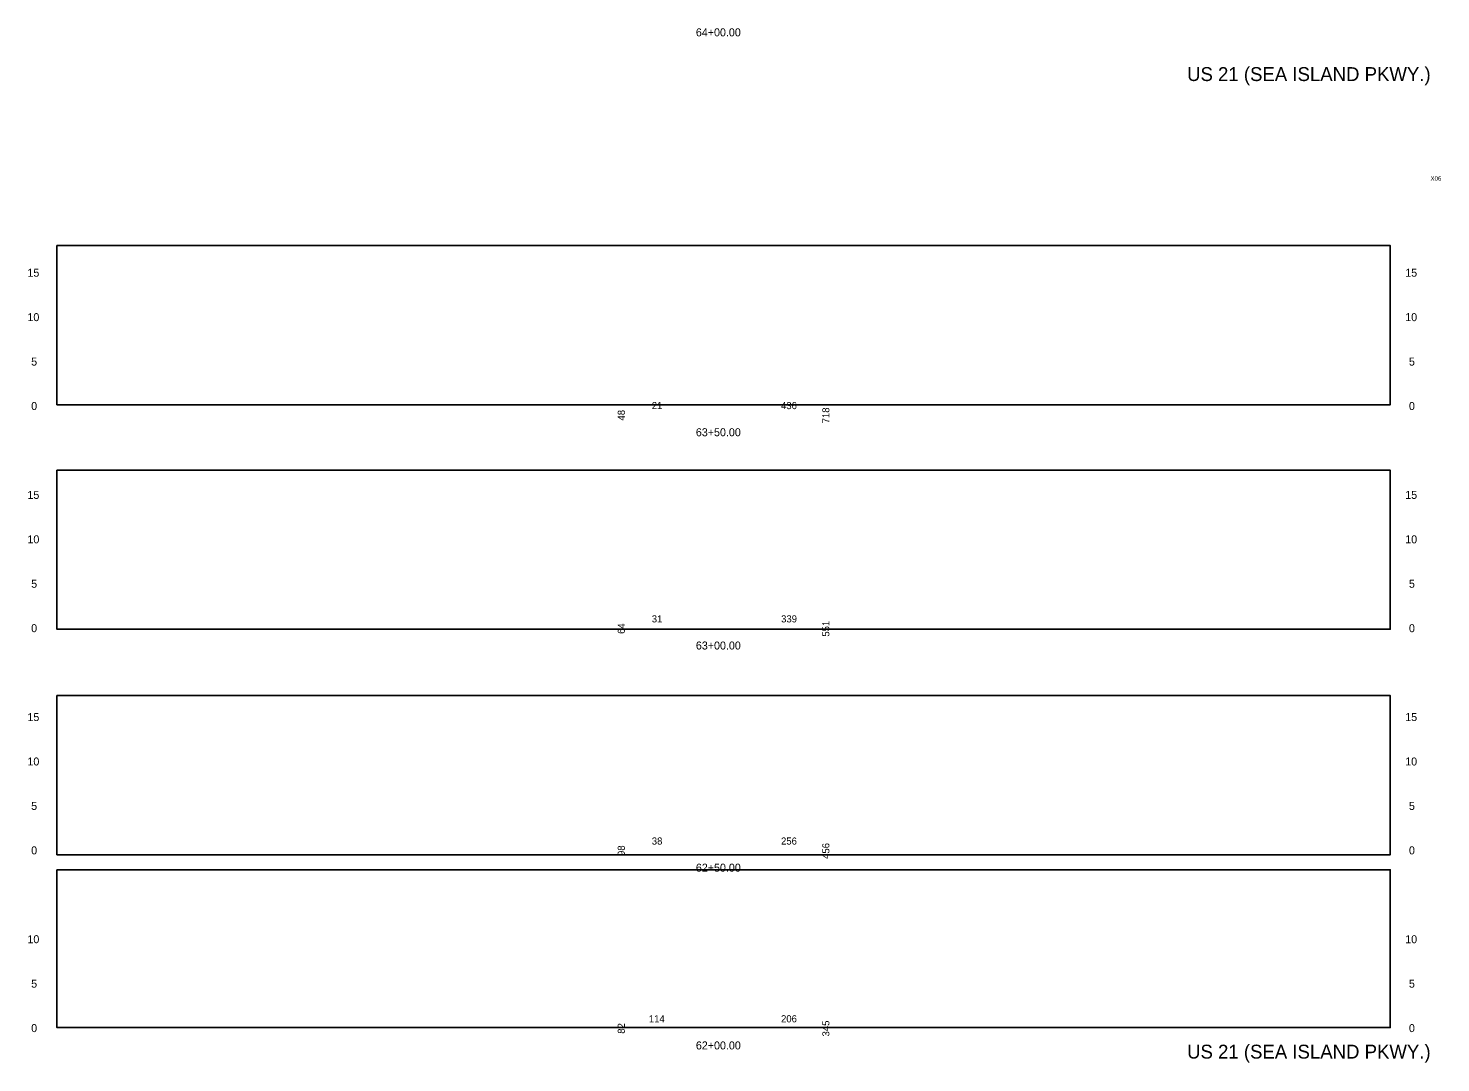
# Model space of a CAD drawing. Extents: x 971 to 1131, y 2203 to 6043.
# Drawn here: x 971.5 to 1130.4, y 2753.4 to 2869.8 of the extents above; entities that cross this region are included whole.
import ezdxf

# ---------------------------------------------------------------- set-up
doc = ezdxf.new("R2010")
doc.units = 0
for name, color, linetype in [('RD_SHT_Misc1', 7, 'Continuous'), ('RD_SHT_ShtClip', 7, 'Continuous'), ('RD_SHT_TX', 7, 'Continuous'), ('RD_XS_TX_Station', 7, 'Continuous')]:
    doc.layers.add(name, color=color, linetype=linetype)

msp = doc.modelspace()

# ---------------------------------------------------------------- linework, layer by layer
at = {"layer": 'RD_SHT_ShtClip'}
for points in [[(974.73, 2845.38), (1124.73, 2845.38), (1124.73, 2827.47), (974.73, 2827.47)], [(974.73, 2820.1), (1124.73, 2820.1), (1124.73, 2802.2), (974.73, 2802.2)], [(974.73, 2794.74), (1124.73, 2794.74), (1124.73, 2776.83), (974.73, 2776.83)], [(974.73, 2775.13), (1124.73, 2775.13), (1124.73, 2757.37), (974.73, 2757.37)]]:
    msp.add_lwpolyline(points, close=True, dxfattribs=at)

# ---------------------------------------------------------------- texts
at = {"layer": 'RD_SHT_Misc1'}
for s, p in [('21', (1041.66, 2826.97)), ('436', (1056.2, 2826.97)), ('31', (1041.66, 2802.97)), ('339', (1056.21, 2802.97)), ('38', (1041.66, 2777.97)), ('256', (1056.2, 2777.97)), ('114', (1041.33, 2757.97)), ('206', (1056.2, 2757.97))]:
    msp.add_text(s, height=0.8, dxfattribs=at).set_placement(p)
for s, p in [('718', (1061.64, 2825.37)), ('48', (1038.63, 2825.69)), ('551', (1061.64, 2801.37)), ('64', (1038.63, 2801.68)), ('98', (1038.63, 2776.69)), ('456', (1061.64, 2776.36)), ('82', (1038.63, 2756.69)), ('345', (1061.64, 2756.38))]:
    msp.add_text(s, height=0.8, rotation=90, dxfattribs=at).set_placement(p)
at = {"layer": 'RD_SHT_TX'}
for s, height, p in [('US 21 (SEA ISLAND PKWY.)', 1.5625, (1101.88, 2863.89)), ('15', 0.9, (971.42, 2841.87)), ('15', 0.9, (1126.42, 2841.87)), ('10', 0.9, (971.42, 2836.87)), ('10', 0.9, (1126.42, 2836.87)), ('5', 0.9, (971.84, 2831.87)), ('5', 0.9, (1126.84, 2831.87)), ('0', 0.9, (971.84, 2826.87)), ('0', 0.9, (1126.84, 2826.87)), ('15', 0.9, (971.42, 2816.87)), ('15', 0.9, (1126.42, 2816.87)), ('10', 0.9, (971.42, 2811.87)), ('10', 0.9, (1126.42, 2811.87)), ('5', 0.9, (971.84, 2806.87)), ('5', 0.9, (1126.84, 2806.87)), ('0', 0.9, (971.84, 2801.87)), ('0', 0.9, (1126.84, 2801.87)), ('15', 0.9, (971.42, 2791.87)), ('15', 0.9, (1126.42, 2791.87)), ('10', 0.9, (971.42, 2786.87)), ('10', 0.9, (1126.42, 2786.87)), ('5', 0.9, (971.84, 2781.87)), ('5', 0.9, (1126.84, 2781.87)), ('0', 0.9, (971.84, 2776.87)), ('0', 0.9, (1126.84, 2776.87)), ('10', 0.9, (971.42, 2766.87)), ('10', 0.9, (1126.42, 2766.87)), ('5', 0.9, (971.84, 2761.87)), ('5', 0.9, (1126.84, 2761.87)), ('0', 0.9, (971.84, 2756.87)), ('0', 0.9, (1126.84, 2756.87)), ('US 21 (SEA ISLAND PKWY.)', 1.5625, (1101.88, 2753.89))]:
    msp.add_text(s, height=height, dxfattribs=at).set_placement(p)
msp.add_text('X06', height=0.5, rotation=360, dxfattribs=at).set_placement((1129.26, 2852.68))
at = {"layer": 'RD_XS_TX_Station'}
for s, p in [('64+00.00', (1046.62, 2868.92)), ('63+50.00', (1046.62, 2823.92)), ('63+00.00', (1046.62, 2799.92)), ('62+50.00', (1046.62, 2774.92)), ('62+00.00', (1046.62, 2754.92))]:
    msp.add_text(s, height=0.9, dxfattribs=at).set_placement(p)

doc.saveas('drawing.dxf')
